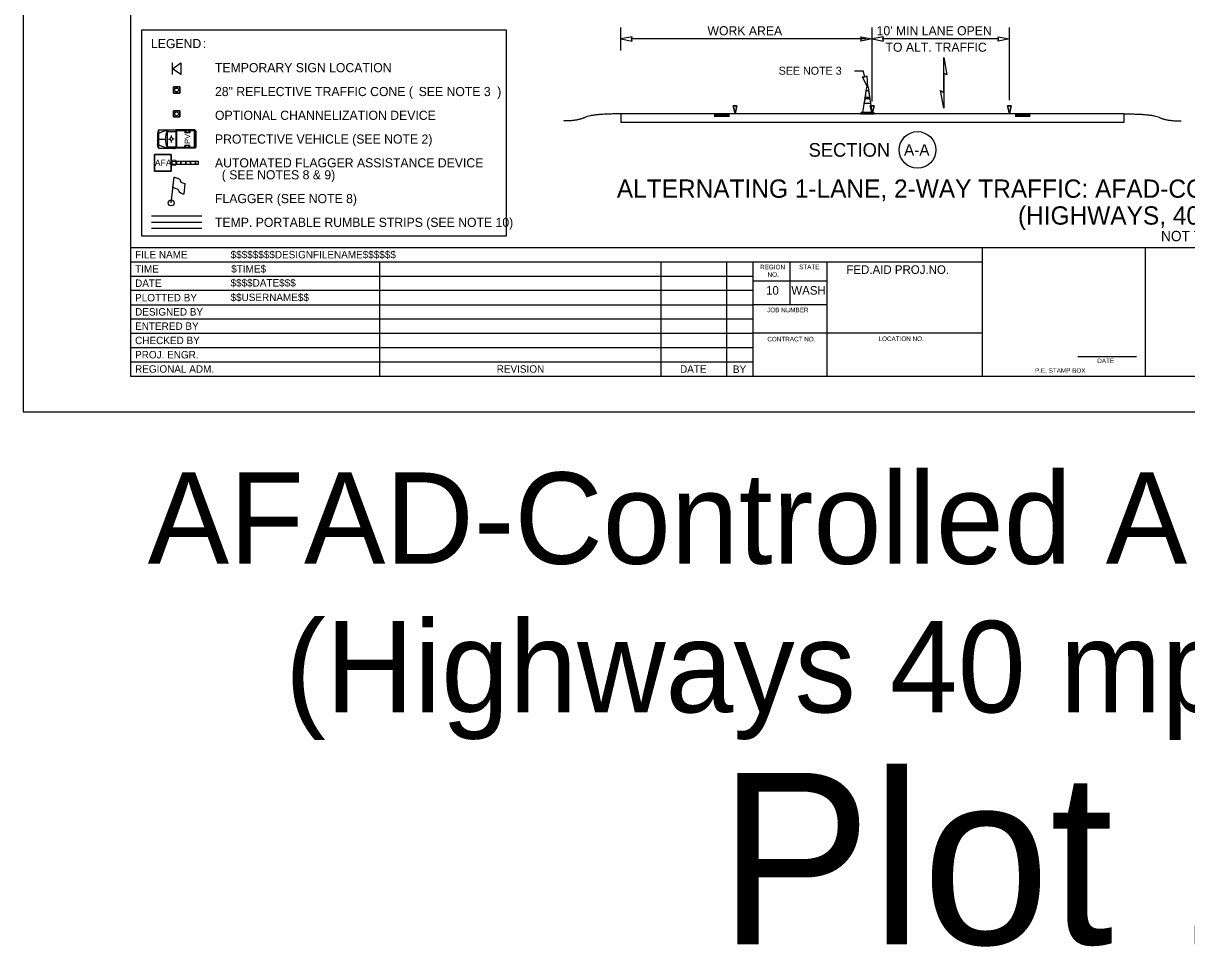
# Model space of a CAD drawing. Extents: x 99999.1 to 100095.7, y 99995 to 100010.7.
# Drawn here: x 99999.06 to 100009.24, y 99995.01 to 100003.09 of the extents above; entities that cross this region are included whole.
import ezdxf

# ---------------------------------------------------------------- set-up
doc = ezdxf.new("R2010")
doc.units = 0
for name, color, linetype in [('SH_DE_DetailHeading1Text', 7, 'Continuous'), ('SH_GI_PlotLimits', 7, 'Continuous'), ('SH_GI_SheetBorder', 7, 'Continuous'), ('SH_GI_SheetLocationText', 7, 'Continuous'), ('SH_GI_SheetTextInCells', 7, 'Continuous'), ('SH_GI_TitleBlockText', 7, 'Continuous'), ('TR_WZ_AFAD', 7, 'Continuous'), ('TR_WZ_FlaggingStation', 7, 'Continuous'), ('TR_WZ_PortableSignMountBlk-Org', 7, 'Continuous'), ('TR_WZ_ProtectiveVehicle', 7, 'Continuous'), ('TR_WZ_TrafficCone', 7, 'Continuous'), ('TR_WZ_TrafficConeElev', 7, 'Continuous'), ('TR_WZ_WorkZoneDetails', 7, 'Continuous'), ('TR_WZ_WorkZoneTextCurrent', 7, 'Continuous')]:
    doc.layers.add(name, color=color, linetype=linetype)

msp = doc.modelspace()

# ---------------------------------------------------------------- linework, layer by layer
at = {"layer": 'SH_GI_PlotLimits'}
msp.add_lwpolyline([(99999.062, 99999.687), (100016.062, 99999.687), (100016.062, 100010.687), (99999.062, 100010.687)], close=True, dxfattribs=at)
at = {"layer": 'SH_GI_SheetBorder'}
for p, q in [((100000, 100010.375), (100000, 100000)), ((100000, 100001.126), (100015.75, 100001.126)), ((100007.457, 100000), (100007.457, 100001.126)), ((100008.883, 100000), (100008.883, 100001.126)), ((100000, 100001.001), (100007.457, 100001.001)), ((100002.179, 100001.001), (100002.179, 100000)), ((100004.641, 100001.001), (100004.641, 100000)), ((100005.216, 100001.001), (100005.216, 100000)), ((100005.445, 100001.001), (100005.445, 100000)), ((100005.772, 100000.625), (100005.772, 100001.001)), ((100006.096, 100000), (100006.096, 100001.001)), ((100000, 100000.876), (100002.182, 100000.876)), ((100002.182, 100000.876), (100005.447, 100000.876)), ((100006.096, 100000.831), (100005.447, 100000.831)), ((100000, 100000.751), (100002.182, 100000.751)), ((100002.182, 100000.751), (100005.447, 100000.751)), ((100000, 100000.625), (100005.447, 100000.625)), ((100006.096, 100000.625), (100005.447, 100000.625)), ((100000, 100000.5), (100005.447, 100000.5)), ((100000, 100000.375), (100005.447, 100000.375)), ((100007.457, 100000.375), (100005.447, 100000.375)), ((100000, 100000.25), (100005.447, 100000.25)), ((100000, 100000.125), (100005.447, 100000.125)), ((100008.29, 100000.173), (100008.802, 100000.173)), ((100000, 100000), (100015.75, 100000))]:
    msp.add_line(p, q, dxfattribs=at)
at = {"layer": 'TR_WZ_AFAD'}
for p, q in [((100000.212, 100001.795), (100000.212, 100001.939)), ((100000.212, 100001.939), (100000.356, 100001.939)), ((100000.356, 100001.939), (100000.212, 100001.939)), ((100000.212, 100001.939), (100000.212, 100001.795)), ((100000.356, 100001.939), (100000.356, 100001.795)), ((100000.356, 100001.872), (100000.356, 100001.939)), ((100000.399, 100001.879), (100000.356, 100001.879)), ((100000.356, 100001.879), (100000.356, 100001.872)), ((100000.356, 100001.872), (100000.356, 100001.867)), ((100000.441, 100001.879), (100000.399, 100001.879)), ((100000.399, 100001.855), (100000.441, 100001.855)), ((100000.484, 100001.879), (100000.441, 100001.879)), ((100000.441, 100001.867), (100000.441, 100001.879)), ((100000.441, 100001.855), (100000.441, 100001.867)), ((100000.441, 100001.855), (100000.484, 100001.855)), ((100000.527, 100001.879), (100000.484, 100001.879)), ((100000.484, 100001.879), (100000.484, 100001.867)), ((100000.484, 100001.867), (100000.484, 100001.855)), ((100000.484, 100001.855), (100000.527, 100001.855)), ((100000.569, 100001.879), (100000.527, 100001.879)), ((100000.527, 100001.867), (100000.527, 100001.879)), ((100000.527, 100001.855), (100000.527, 100001.867)), ((100000.527, 100001.855), (100000.569, 100001.855)), ((100000.569, 100001.879), (100000.569, 100001.867)), ((100000.569, 100001.867), (100000.569, 100001.855)), ((100000.569, 100001.855), (100000.596, 100001.855)), ((100000.356, 100001.795), (100000.212, 100001.795)), ((100000.212, 100001.795), (100000.356, 100001.795))]:
    msp.add_line(p, q, dxfattribs=at)
for points in [[(100000.356, 100001.855), (100000.596, 100001.855), (100000.596, 100001.879), (100000.356, 100001.879)], [(100000.356, 100001.795), (100000.356, 100001.861), (100000.356, 100001.872)], [(100000.356, 100001.867), (100000.356, 100001.861), (100000.356, 100001.855), (100000.399, 100001.855)], [(100000.399, 100001.855), (100000.399, 100001.867), (100000.399, 100001.879)], [(100000.399, 100001.879), (100000.399, 100001.867), (100000.399, 100001.855)], [(100000.441, 100001.879), (100000.441, 100001.867), (100000.441, 100001.855)], [(100000.484, 100001.855), (100000.484, 100001.867), (100000.484, 100001.879)], [(100000.527, 100001.879), (100000.527, 100001.867), (100000.527, 100001.855)], [(100000.569, 100001.855), (100000.569, 100001.867), (100000.569, 100001.879)], [(100000.596, 100001.855), (100000.596, 100001.879), (100000.569, 100001.879)]]:
    msp.add_lwpolyline(points, dxfattribs=at)
at = {"layer": 'TR_WZ_FlaggingStation'}
for p, q in [((100000.357, 100001.516), (100000.383, 100001.741)), ((100000.372, 100001.65), (100000.383, 100001.741)), ((100000.372, 100001.65), (100000.372, 100001.65)), ((100000.477, 100001.687), (100000.467, 100001.593))]:
    msp.add_line(p, q, dxfattribs=at)
for points in [[(100000.383, 100001.741), (100000.387, 100001.74), (100000.402, 100001.737), (100000.413, 100001.734), (100000.42, 100001.729), (100000.427, 100001.725), (100000.432, 100001.72), (100000.435, 100001.714), (100000.436, 100001.709), (100000.44, 100001.701), (100000.449, 100001.695), (100000.458, 100001.691), (100000.477, 100001.687)], [(100000.467, 100001.593), (100000.46, 100001.594), (100000.446, 100001.598), (100000.433, 100001.606), (100000.428, 100001.615), (100000.425, 100001.623), (100000.418, 100001.632), (100000.409, 100001.637), (100000.395, 100001.642), (100000.372, 100001.65)]]:
    msp.add_lwpolyline(points, dxfattribs=at)
msp.add_circle((100000.357, 100001.516), 0.026, dxfattribs=at)
at = {"layer": 'TR_WZ_PortableSignMountBlk-Org'}
msp.add_line((100000.368, 100002.641), (100000.368, 100002.741), dxfattribs=at)
msp.add_lwpolyline([(100000.368, 100002.691), (100000.44, 100002.741), (100000.44, 100002.641)], close=True, dxfattribs=at)
at = {"layer": 'TR_WZ_ProtectiveVehicle'}
for p, q in [((100000.245, 100002.155), (100000.238, 100002.123)), ((100000.245, 100002.155), (100000.245, 100001.995)), ((100000.245, 100002.155), (100000.396, 100002.155)), ((100000.245, 100002.126), (100000.321, 100002.155)), ((100000.321, 100002.155), (100000.321, 100001.995)), ((100000.322, 100002.155), (100000.322, 100001.995)), ((100000.322, 100002.155), (100000.332, 100002.142)), ((100000.322, 100002.142), (100000.396, 100002.142)), ((100000.376, 100002.157), (100000.385, 100002.157)), ((100000.396, 100002.155), (100000.396, 100001.995)), ((100000.563, 100002.155), (100000.398, 100002.155)), ((100000.398, 100002.155), (100000.398, 100001.995)), ((100000.558, 100002.148), (100000.403, 100002.148)), ((100000.403, 100002.148), (100000.403, 100002.001)), ((100000.477, 100002.148), (100000.477, 100002.13)), ((100000.485, 100002.148), (100000.485, 100002.13)), ((100000.512, 100002.148), (100000.512, 100002.13)), ((100000.521, 100002.148), (100000.521, 100002.13)), ((100000.558, 100002.148), (100000.558, 100002.001)), ((100000.563, 100002.155), (100000.563, 100001.995)), ((100000.567, 100002.152), (100000.563, 100002.152)), ((100000.563, 100002.152), (100000.563, 100001.998)), ((100000.571, 100002.147), (100000.571, 100002.002)), ((100000.238, 100002.123), (100000.238, 100002.027)), ((100000.245, 100002.075), (100000.306, 100002.075)), ((100000.334, 100002.075), (100000.344, 100002.075)), ((100000.358, 100002.107), (100000.358, 100002.094)), ((100000.359, 100002.044), (100000.359, 100002.056)), ((100000.37, 100002.075), (100000.37, 100002.075)), ((100000.383, 100002.074), (100000.371, 100002.075)), ((100000.521, 100002.13), (100000.477, 100002.13)), ((100000.571, 100002.086), (100000.563, 100002.083)), ((100000.571, 100002.064), (100000.563, 100002.067)), ((100000.569, 100002.075), (100000.565, 100002.075)), ((100000.567, 100002.077), (100000.567, 100002.073)), ((100000.245, 100001.995), (100000.238, 100002.027)), ((100000.245, 100002.024), (100000.321, 100001.995)), ((100000.245, 100001.995), (100000.396, 100001.995)), ((100000.322, 100002.007), (100000.396, 100002.007)), ((100000.33, 100002.007), (100000.322, 100001.995)), ((100000.376, 100001.993), (100000.385, 100001.993)), ((100000.563, 100001.995), (100000.398, 100001.995)), ((100000.558, 100002.001), (100000.403, 100002.001)), ((100000.477, 100002.001), (100000.477, 100002.02)), ((100000.521, 100002.02), (100000.477, 100002.02)), ((100000.485, 100002.001), (100000.485, 100002.02)), ((100000.512, 100002.001), (100000.512, 100002.02)), ((100000.521, 100002.001), (100000.521, 100002.02)), ((100000.567, 100001.998), (100000.563, 100001.998))]:
    msp.add_line(p, q, dxfattribs=at)
for centre, major_axis, start_param, end_param in [((100000.429, 100002.075), (0, -0.168), 4.215667, 5.208926), ((100000.567, 100002.147), (0, 0.00488), 4.712389, 6.283185), ((100000.567, 100002.002), (0, -0.00488), 0, 1.570796)]:
    msp.add_ellipse(centre, major_axis=major_axis, ratio=0.73155, start_param=start_param, end_param=end_param, dxfattribs=at)
for centre, major_axis in [((100000.358, 100002.075), (0, 0.0154)), ((100000.567, 100002.075), (0, 0.00225))]:
    msp.add_ellipse(centre, major_axis=major_axis, ratio=0.73155, dxfattribs=at)
at = {"layer": 'TR_WZ_TrafficCone'}
for points in [[(100000.377, 100002.531), (100000.431, 100002.531), (100000.431, 100002.478), (100000.377, 100002.478), (100000.377, 100002.531)], [(100000.377, 100002.478), (100000.431, 100002.478), (100000.431, 100002.531), (100000.377, 100002.531), (100000.377, 100002.478)], [(100000.377, 100002.323), (100000.431, 100002.323), (100000.431, 100002.27), (100000.377, 100002.27), (100000.377, 100002.323)], [(100000.377, 100002.27), (100000.431, 100002.27), (100000.431, 100002.323), (100000.377, 100002.323), (100000.377, 100002.27)]]:
    msp.add_lwpolyline(points, dxfattribs=at)
for centre in [(100000.404, 100002.505), (100000.404, 100002.296)]:
    msp.add_circle(centre, 0.0167, dxfattribs=at)
at = {"layer": 'TR_WZ_TrafficConeElev'}
for p, q in [((100006.436, 100002.498), (100006.428, 100002.443)), ((100006.428, 100002.443), (100006.47, 100002.443)), ((100006.462, 100002.498), (100006.436, 100002.498)), ((100006.47, 100002.443), (100006.462, 100002.498)), ((100006.425, 100002.427), (100006.42, 100002.389)), ((100006.42, 100002.389), (100006.478, 100002.389)), ((100006.472, 100002.427), (100006.425, 100002.427)), ((100006.478, 100002.389), (100006.472, 100002.427)), ((100006.395, 100002.308), (100006.391, 100002.304)), ((100006.391, 100002.304), (100006.391, 100002.296)), ((100006.391, 100002.296), (100006.507, 100002.296)), ((100006.407, 100002.308), (100006.395, 100002.308)), ((100006.507, 100002.304), (100006.503, 100002.308)), ((100006.507, 100002.296), (100006.507, 100002.304))]:
    msp.add_line(p, q, dxfattribs=at)
msp.add_lwpolyline([(100006.407, 100002.308), (100006.491, 100002.308), (100006.457, 100002.529), (100006.441, 100002.529)], close=True, dxfattribs=at)
msp.add_lwpolyline([(100006.407, 100002.308), (100006.491, 100002.308), (100006.457, 100002.529), (100006.441, 100002.529)], close=True, dxfattribs=at)
msp.add_lwpolyline([(100006.503, 100002.308), (100006.491, 100002.308), (100006.407, 100002.308)], dxfattribs=at)
at = {"layer": 'TR_WZ_WorkZoneDetails'}
for p, q in [((100004.291, 100002.851), (100004.291, 100003.051)), ((100006.491, 100002.405), (100006.491, 100003.051)), ((100007.691, 100002.415), (100007.691, 100003.051)), ((100006.439, 100002.951), (100004.384, 100002.951)), ((100007.597, 100002.951), (100006.584, 100002.951)), ((100006.336, 100002.672), (100006.412, 100002.672)), ((100006.425, 100002.62), (100006.412, 100002.672)), ((100007.116, 100002.652), (100007.116, 100002.483)), ((100007.116, 100002.483), (100007.116, 100002.652)), ((100004.291, 100002.295), (100004.291, 100002.22)), ((100008.691, 100002.295), (100004.291, 100002.295)), ((100005.108, 100002.29), (100005.241, 100002.29)), ((100005.108, 100002.285), (100005.241, 100002.285)), ((100005.108, 100002.279), (100005.241, 100002.279)), ((100005.108, 100002.274), (100005.241, 100002.274)), ((100007.874, 100002.29), (100007.741, 100002.29)), ((100007.874, 100002.284), (100007.741, 100002.284)), ((100007.874, 100002.278), (100007.741, 100002.278)), ((100007.874, 100002.273), (100007.741, 100002.273)), ((100008.691, 100002.295), (100008.691, 100002.22)), ((100008.691, 100002.22), (100004.291, 100002.22)), ((100000.624, 100001.401), (100000.184, 100001.401)), ((100000.624, 100001.346), (100000.184, 100001.346)), ((100000.624, 100001.291), (100000.184, 100001.291))]:
    msp.add_line(p, q, dxfattribs=at)
for points in [[(100004.291, 100002.951), (100004.389, 100002.932), (100004.384, 100002.951), (100004.389, 100002.971)], [(100006.491, 100002.951), (100006.392, 100002.932), (100006.397, 100002.951), (100006.392, 100002.971)], [(100006.491, 100002.951), (100006.589, 100002.932), (100006.584, 100002.951), (100006.589, 100002.971)], [(100007.691, 100002.951), (100007.592, 100002.932), (100007.597, 100002.951), (100007.592, 100002.971)], [(100007.116, 100002.789), (100007.143, 100002.636), (100007.116, 100002.652)], [(100006.449, 100002.529), (100006.406, 100002.619), (100006.426, 100002.62), (100006.443, 100002.629)], [(100007.116, 100002.345), (100007.089, 100002.499), (100007.116, 100002.483)], [(100005.291, 100002.295), (100005.274, 100002.365), (100005.307, 100002.365)], [(100006.491, 100002.295), (100006.474, 100002.365), (100006.507, 100002.365)], [(100007.691, 100002.295), (100007.674, 100002.365), (100007.707, 100002.365)]]:
    msp.add_lwpolyline(points, close=True, dxfattribs=at)
for points in [[(100005.307, 100002.365), (100005.274, 100002.365), (100005.291, 100002.295), (100005.307, 100002.365)], [(100006.507, 100002.365), (100006.474, 100002.365), (100006.491, 100002.295), (100006.507, 100002.365)], [(100007.707, 100002.365), (100007.674, 100002.365), (100007.691, 100002.295), (100007.707, 100002.365)]]:
    msp.add_lwpolyline(points, dxfattribs=at)
msp.add_circle((100006.887, 100001.98), 0.16, dxfattribs=at)
for points in [[(100004.291, 100002.295), (100004.04, 100002.295), (100003.914, 100002.233), (100003.789, 100002.233)], [(100008.691, 100002.295), (100008.942, 100002.296), (100009.067, 100002.233), (100009.193, 100002.234)]]:
    msp.add_open_spline(points, degree=2, dxfattribs=at)
at = {"layer": 'TR_WZ_WorkZoneTextCurrent'}
msp.add_lwpolyline([(100000.1, 100003.031), (100003.289, 100003.031), (100003.289, 100001.226), (100000.1, 100001.226)], close=True, dxfattribs=at)

# ---------------------------------------------------------------- texts
at = {"layer": 'SH_DE_DetailHeading1Text'}
for s, height, p in [('ALTERNATING 1-LANE, 2-WAY TRAFFIC: AFAD-CONTROLLED + TEMPORARY RUMBLE STRIPS', 0.16, (100004.256, 100001.561)), ('(HIGHWAYS, 40 MPH OR LESS)', 0.16, (100007.766, 100001.326)), ('NOT TO SCALE', 0.09, (100009.017, 100001.181))]:
    msp.add_text(s, height=height, rotation=360, dxfattribs=at).set_placement(p)
at = {"layer": 'SH_GI_SheetLocationText'}
for s, height, p in [('AFAD-Controlled Alt Traffic + RS', 0.8, (100000.151, 99998.357)), ('(Highways 40 mph or Less)', 0.8, (100001.353, 99997.057)), ('Plot 1', 1.5, (100005.145, 99995.027))]:
    msp.add_text(s, height=height, dxfattribs=at).set_placement(p)
at = {"layer": 'SH_GI_SheetTextInCells'}
for s, height, p in [('FILE NAME', 0.0651, (100000.041, 100001.031)), ('TIME', 0.0651, (100000.041, 100000.906)), ('REGION', 0.04, (100005.51, 100000.935)), ('STATE', 0.04, (100005.851, 100000.936)), ('FED.AID PROJ.NO.', 0.07506, (100006.265, 100000.895)), ('DATE', 0.0651, (100000.041, 100000.781)), ('NO.', 0.04, (100005.575, 100000.869)), ('PLOTTED BY', 0.0651, (100000.041, 100000.654)), ('10', 0.0751, (100005.562, 100000.713)), ('WASH', 0.0751, (100005.783, 100000.713)), ('DESIGNED BY', 0.06505, (100000.041, 100000.53)), ('JOB NUMBER', 0.04, (100005.571, 100000.559)), ('ENTERED BY', 0.0651, (100000.041, 100000.405)), ('CHECKED BY', 0.0651, (100000.041, 100000.28)), ('CONTRACT NO.', 0.04003, (100005.573, 100000.304)), ('LOCATION NO.', 0.04003, (100006.546, 100000.307)), ('PROJ. ENGR.', 0.06505, (100000.041, 100000.155)), ('DATE', 0.04, (100008.46, 100000.114)), ('REGIONAL ADM.', 0.06505, (100000.041, 100000.03)), ('REVISION', 0.0651, (100003.205, 100000.03)), ('DATE', 0.0651, (100004.809, 100000.03)), ('BY', 0.0651, (100005.272, 100000.028)), ('P.E. STAMP BOX', 0.04003, (100007.915, 100000.029))]:
    msp.add_text(s, height=height, dxfattribs=at).set_placement(p)
at = {"layer": 'SH_GI_TitleBlockText'}
for s, height, p in [('$$$$$$$$DESIGNFILENAME$$$$$$', 0.06505, (100000.877, 100001.031)), ('$TIME$', 0.0651, (100000.882, 100000.906)), ('$$$$DATE$$$', 0.06505, (100000.876, 100000.784)), ('$$USERNAME$$', 0.06505, (100000.876, 100000.657))]:
    msp.add_text(s, height=height, dxfattribs=at).set_placement(p)
at = {"layer": 'TR_WZ_AFAD'}
msp.add_text('AFAD', height=0.056, dxfattribs=at).set_placement((100000.214, 100001.839))
at = {"layer": 'TR_WZ_ProtectiveVehicle'}
msp.add_text('PV', height=0.048, rotation=90, dxfattribs=at).set_placement((100000.523, 100002.032))
at = {"layer": 'TR_WZ_WorkZoneDetails'}
for s, p in [('WORK AREA', (100005.049, 100002.983)), ("10' MIN LANE OPEN", (100006.529, 100002.983)), ('TO ALT. TRAFFIC', (100006.607, 100002.839))]:
    msp.add_text(s, height=0.08, dxfattribs=at).set_placement(p)
for s, height, p in [('SECTION', 0.12, (100005.934, 100001.92)), ('A-A', 0.1, (100006.769, 100001.93))]:
    msp.add_text(s, height=height, rotation=360, dxfattribs=at).set_placement(p)
at = {"layer": 'TR_WZ_WorkZoneTextCurrent'}
for s, p in [('LEGEND', (100000.18, 100002.871)), (':', (100000.633, 100002.871)), ('TEMPORARY SIGN LOCATION ', (100000.74, 100002.66)), ('28" REFLECTIVE TRAFFIC CONE (', (100000.74, 100002.451)), ('SEE NOTE 3', (100002.522, 100002.451)), (')', (100003.21, 100002.451)), ('OPTIONAL CHANNELIZATION DEVICE', (100000.74, 100002.243)), ('PROTECTIVE VEHICLE (SEE NOTE 2)', (100000.74, 100002.035)), ('AUTOMATED FLAGGER ASSISTANCE DEVICE', (100000.74, 100001.827)), ('  ( SEE NOTES 8 & 9)', (100000.74, 100001.722)), ('FLAGGER (SEE NOTE 8)', (100000.74, 100001.514)), ('TEMP. PORTABLE RUMBLE STRIPS (SEE NOTE 10)', (100000.74, 100001.306))]:
    msp.add_text(s, height=0.08, rotation=360, dxfattribs=at).set_placement(p)
msp.add_text('SEE NOTE 3', height=0.07, dxfattribs=at).set_placement((100005.672, 100002.638))

doc.saveas('drawing.dxf')
